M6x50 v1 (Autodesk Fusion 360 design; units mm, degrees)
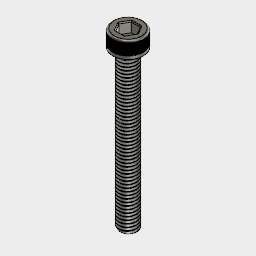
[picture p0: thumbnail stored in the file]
sketch "スケッチ1"
  circle C1 centre (0, 0) radius 3
  circle C2 centre (0, 0) radius 5
  dimension "d1" diameter C1 = 6
  dimension "d2" diameter C2 = 10
extrude "押し出し1" new body sketch "スケッチ1" blind 5.8
sketch "スケッチ2" plane through (0, 0, 5.8) normal (0, 0, 1) x axis (-1, 0, 0)
  line L1 (-1.4722, -2.55) -> (-2.9445, 0)
  line L2 (1.4722, -2.55) -> (-1.4722, -2.55)
  line L3 (2.9445, 0) -> (1.4722, -2.55)
  line L4 (1.4722, 2.55) -> (2.9445, 0)
  line L5 (-1.4722, 2.55) -> (1.4722, 2.55)
  line L6 (-2.9445, 0) -> (-1.4722, 2.55)
  circle C1 centre (0, 0) radius 5
  dimension "d5" distance L2 L5 = 5.1
work_plane "作業平面" sketch "スケッチ2" AlongDistance -0.75
extrude "押し出し2" cut sketch "スケッチ2" profile of L1 L2 L3 L4 L5 L6 against normal blind 3.3
chamfer "面取り" distance 0.3
sketch "スケッチ3" plane through (0, 0, 5.05) normal (0, 0, 1) x axis (1, 0, 0)
  line L1 (-0.05, 4.9497) -> (-0.05, 4.9997)
  line L2 (0.05, 4.9497) -> (-0.05, 4.9497)
  line L3 (0.05, 4.9997) -> (0.05, 4.9497)
  circle C1 centre (0, 0) radius 5
  point P4 (-0.05, 4.9497)
  point P5 (0.05, 4.9497)
  point P3 (-0.05, 4.9997)
  point P6 (0.05, 4.9997)
  dimension "d18" distance P4 P5 = 0.1
  dimension "d19" distance P3 P4 = 0.05
  dimension "d20" distance P5 P6 = 0.05 (= "d19")
extrude "押し出し3" cut sketch "スケッチ3" against normal blind 3.6
work_axis "作業軸"
circular_pattern "C パターン" countU 100 TotalAngle 360
fillet "フィレット1" radius 0.6
extrude "押し出し4" add sketch "スケッチ1" profile of C1 blind -50
thread "ねじ"
fillet "フィレット2" sketch "スケッチ3" radius 0.5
